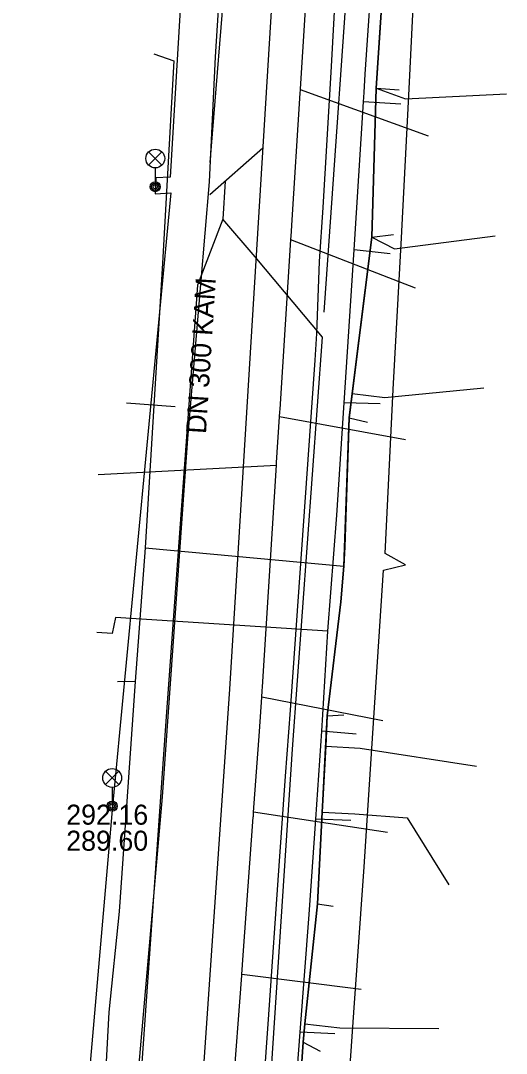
# Model space of a CAD drawing. Extents: x -595540 to -593988, y -1160850 to -1159202.
# Drawn here: x -594722.37 to -594702.98, y -1160244.04 to -1160202.8 of the extents above; entities that cross this region are included whole.
import ezdxf

# ---------------------------------------------------------------- set-up
doc = ezdxf.new("R2010")
doc.units = 0
for name, color, linetype in [('BVK-SPLASKOVA_popisy', 7, 'Continuous'), ('BVK-SPLASKOVA_trasa sítě', 7, 'Continuous'), ('BVK-VODOVOD_trasa sítě', 7, 'Continuous'), ('DSP-DESTOVA-BVK_trasa podzemní sítě', 7, 'Continuous'), ('DSP-SDEL-VODAFONE_kabel', 7, 'Continuous'), ('DSP-VODOVOD-BVK_trasa sítě', 7, 'Continuous'), ('EON-NN_kabel', 7, 'Continuous'), ('INNOGY-STL_trasa sítě', 7, 'Continuous'), ('SPLASKOVA_neprovozovaná  trasa sítě', 7, 'Continuous'), ('TSB_kabel VO', 7, 'Continuous'), ('TSB_lampy VO', 7, 'Continuous')]:
    doc.layers.add(name, color=color, linetype=linetype)

msp = doc.modelspace()

# ---------------------------------------------------------------- linework, layer by layer
at = {"layer": 'BVK-SPLASKOVA_popisy'}
msp.add_line((-594720.547, -1160234.111), (-594720.547, -1160234.111), dxfattribs=at)
at = {"layer": 'BVK-SPLASKOVA_trasa sítě'}
for points in [[(-594712.83, -1160231.19), (-594712.743, -1160229.818), (-594712.727, -1160229.566), (-594712.717, -1160229.404), (-594712.155, -1160220.556), (-594712.149, -1160220.462), (-594712.148, -1160220.445), (-594712.032, -1160218.619), (-594712.02, -1160218.426), (-594712.013, -1160218.316), (-594711.583, -1160211.559), (-594711.561, -1160211.22), (-594711.545, -1160210.968), (-594711.21, -1160205.691), (-594711.202, -1160205.559), (-594711.2, -1160205.521), (-594710.703, -1160197.698), (-594710.69, -1160197.488), (-594710.689, -1160197.479), (-594710.62, -1160196.39)], [(-594713.892, -1160245.671), (-594713.544, -1160240.935), (-594713.541, -1160240.891), (-594713.485, -1160240.126), (-594713.081, -1160234.611), (-594713.078, -1160234.574), (-594713.066, -1160234.406), (-594712.83, -1160231.19)]]:
    msp.add_lwpolyline(points, dxfattribs=at)
at = {"layer": 'BVK-VODOVOD_trasa sítě'}
msp.add_lwpolyline([(-594709.816, -1160201.699), (-594709.974, -1160204.626), (-594710.309, -1160210.266), (-594710.446, -1160212.418), (-594710.56, -1160215.3), (-594710.629, -1160216.362), (-594711.614, -1160230.332), (-594711.813, -1160232.98), (-594712.055, -1160236.55), (-594712.467, -1160242.489), (-594712.88, -1160248.322), (-594713.33, -1160254.72), (-594713.523, -1160257.981), (-594713.991, -1160263.88), (-594714.207, -1160266.837), (-594714.67, -1160272.908), (-594715.035, -1160278.113), (-594715.11, -1160279.01)], dxfattribs=at)
at = {"layer": 'DSP-DESTOVA-BVK_trasa podzemní sítě'}
for p, q in [((-594714.82, -1160209.75), (-594712.702, -1160207.877)), ((-594714.206, -1160209.207), (-594714.3, -1160210.73))]:
    msp.add_line(p, q, dxfattribs=at)
for points in [[(-594704.23, -1160062.12), (-594706.74, -1160074.53), (-594711.03, -1160081.92), (-594718.05, -1160094.02), (-594717.94, -1160110.41), (-594717.76, -1160137.04), (-594717.39, -1160159.05), (-594717.01, -1160181.31), (-594711.98, -1160196.12), (-594714.03, -1160229.5), (-594715.79, -1160255.02), (-594716.16, -1160260.4)], [(-594710.25, -1160214.442), (-594709.04, -1160197.18), (-594710.57, -1160191.56), (-594714.69, -1160189.7), (-594715.64, -1160189.34), (-594715.69, -1160190.57), (-594714.35, -1160196.02), (-594714.13, -1160200.12), (-594714.82, -1160208.46)], [(-594713.357, -1160259.91), (-594713.06, -1160255.38), (-594711.52, -1160231.9), (-594710.32, -1160215.44), (-594713.01, -1160212.23), (-594714.3, -1160210.73), (-594715.31, -1160213.36), (-594716.57, -1160230.78), (-594718.31, -1160255.59), (-594718.363, -1160256.34)]]:
    msp.add_lwpolyline(points, dxfattribs=at)
at = {"layer": 'DSP-SDEL-VODAFONE_kabel'}
for p, q in [((-594708.17, -1160205.5), (-594707.26, -1160205.57)), ((-594708.35, -1160211.45), (-594707.49, -1160211.34)), ((-594709.25, -1160218.66), (-594708.52, -1160218.83)), ((-594717.4, -1160223.86), (-594709.46, -1160224.59)), ((-594717.4, -1160223.86), (-594709.46, -1160224.59)), ((-594717.4, -1160223.86), (-594709.46, -1160224.59)), ((-594717.79, -1160229.19), (-594718.5, -1160229.21)), ((-594710.13, -1160230.56), (-594709.47, -1160230.52)), ((-594710.52, -1160238.07), (-594709.89, -1160238.17)), ((-594711.09, -1160243.59), (-594710.41, -1160243.96))]:
    msp.add_line(p, q, dxfattribs=at)
for points in [[(-594712.73, -1160179.59), (-594712.44, -1160181.67), (-594712.19, -1160183.44), (-594711.22, -1160185.82), (-594710.3, -1160187.87), (-594708.91, -1160190.02), (-594707.94, -1160192.21), (-594707.79, -1160194.31), (-594707.78, -1160199.43), (-594707.86, -1160200.65), (-594708.17, -1160205.5), (-594708.35, -1160211.45), (-594709.25, -1160218.66), (-594709.43, -1160223.82), (-594709.46, -1160224.59)], [(-594708.17, -1160205.5), (-594707.78, -1160199.43)], [(-594708.17, -1160205.5), (-594707.86, -1160200.65)], [(-594717.05, -1160204.12), (-594716.25, -1160204.41), (-594716.7, -1160212.48), (-594717.4, -1160223.86)], [(-594717.05, -1160204.12), (-594716.25, -1160204.41), (-594716.7, -1160212.48), (-594717.4, -1160223.86)], [(-594708.35, -1160211.45), (-594708.17, -1160205.5)], [(-594708.35, -1160211.45), (-594708.17, -1160205.5)], [(-594708.17, -1160205.5), (-594707, -1160205.92), (-594702.98, -1160205.73)], [(-594709.25, -1160218.66), (-594708.35, -1160211.45)], [(-594709.13, -1160217.69), (-594708.35, -1160211.45)], [(-594708.35, -1160211.45), (-594707.45, -1160211.91), (-594703.43, -1160211.4)], [(-594709.43, -1160223.82), (-594709.25, -1160218.66), (-594709.13, -1160217.69)], [(-594709.13, -1160217.69), (-594707.83, -1160217.85), (-594703.88, -1160217.46)], [(-594709.46, -1160224.59), (-594709.25, -1160218.66)], [(-594717.4, -1160223.86), (-594717.79, -1160229.19)], [(-594717.4, -1160223.86), (-594717.79, -1160229.19)], [(-594709.46, -1160224.59), (-594709.59, -1160226.01), (-594710.13, -1160230.56), (-594710.19, -1160231.78), (-594710.33, -1160234.41), (-594710.52, -1160238.07), (-594711.02, -1160242.87), (-594711.09, -1160243.59), (-594711.52, -1160249.84), (-594711.72, -1160252.62), (-594712.43, -1160262.29), (-594712.39, -1160262.83), (-594712.97, -1160268.59), (-594713.28, -1160274.83), (-594713.5, -1160280.21), (-594713.76, -1160282.85), (-594713.65, -1160283.35), (-594713.15, -1160283.56)], [(-594710.19, -1160231.78), (-594710.13, -1160230.56), (-594709.59, -1160226.01), (-594709.46, -1160224.59)], [(-594710.13, -1160230.56), (-594709.59, -1160226.01), (-594709.46, -1160224.59)], [(-594717.79, -1160229.19), (-594718.44, -1160238.38), (-594718.85, -1160242.4), (-594719.43, -1160253.27), (-594719.4, -1160253.59), (-594720.18, -1160253.56)], [(-594717.79, -1160229.19), (-594718.44, -1160238.38), (-594718.85, -1160242.4), (-594719.43, -1160253.27), (-594719.4, -1160253.59), (-594720.18, -1160253.56)], [(-594710.52, -1160238.07), (-594710.13, -1160230.56)], [(-594710.33, -1160234.41), (-594710.19, -1160231.78)], [(-594710.19, -1160231.78), (-594708.81, -1160231.86), (-594704.17, -1160232.57)], [(-594711.02, -1160242.87), (-594710.52, -1160238.07), (-594710.33, -1160234.41)], [(-594710.33, -1160234.41), (-594709.03, -1160234.48), (-594706.94, -1160234.64), (-594705.28, -1160237.31)], [(-594711.09, -1160243.59), (-594710.52, -1160238.07)], [(-594711.72, -1160252.62), (-594711.52, -1160249.84), (-594711.09, -1160243.59), (-594711.02, -1160242.87)], [(-594711.02, -1160242.87), (-594709.62, -1160243.02), (-594705.67, -1160243.05)], [(-594711.52, -1160249.84), (-594711.09, -1160243.59)]]:
    msp.add_lwpolyline(points, dxfattribs=at)
at = {"layer": 'DSP-VODOVOD-BVK_trasa sítě'}
msp.add_line((-594718.135, -1160218.069), (-594716.2, -1160218.208), dxfattribs=at)
at = {"layer": 'EON-NN_kabel'}
for points in [[(-594720.039, -1160120.667), (-594719.782, -1160133.42), (-594719.761, -1160133.936), (-594719.658, -1160139.618), (-594719.591, -1160150.069), (-594719.56, -1160162.08), (-594719.607, -1160167), (-594719.614, -1160167.25), (-594718.87, -1160174.172), (-594718.702, -1160182.569), (-594718.425, -1160185.217), (-594717.891, -1160187.194), (-594714.08, -1160196.106), (-594714.606, -1160204.241), (-594714.842, -1160209.239), (-594715.703, -1160219.483), (-594716.714, -1160233.804), (-594718.349, -1160252.557), (-594718.321, -1160254.817), (-594720.073, -1160280.009), (-594720.373, -1160279.998), (-594721.51, -1160281.51), (-594722.064, -1160281.517), (-594722.339, -1160281.408)], [(-594722.366, -1160281.584), (-594721.998, -1160281.716), (-594721.507, -1160281.71), (-594721.449, -1160281.634), (-594720.382, -1160280.235), (-594720.089, -1160280.24), (-594719.996, -1160280.873), (-594711.83, -1160282.703), (-594711.602, -1160279.521), (-594711.194, -1160273.462), (-594710.759, -1160267.349), (-594710.441, -1160262.269), (-594709.488, -1160248.553), (-594709.062, -1160242.418), (-594708.649, -1160236.597), (-594708.309, -1160231.252), (-594707.882, -1160224.747), (-594707, -1160224.529), (-594707.82, -1160224.085), (-594707.491, -1160217.538), (-594707.162, -1160211.48), (-594706.858, -1160205.528), (-594706.604, -1160200.359)]]:
    msp.add_lwpolyline(points, dxfattribs=at)
at = {"layer": 'INNOGY-STL_trasa sítě'}
for points in [[(-594713.82, -1160280.77), (-594713.8, -1160280.42), (-594713.4, -1160274.44), (-594713, -1160268.36), (-594712.97, -1160267.96), (-594712.61, -1160262.47), (-594712.36, -1160258.72), (-594712.03, -1160254.11), (-594712, -1160253.82), (-594711.94, -1160252.94), (-594711.76, -1160250.44), (-594711.21, -1160243.2), (-594710.85, -1160238.5), (-594710.58, -1160234.69), (-594710.34, -1160231.17), (-594710.1, -1160227.18), (-594709.74, -1160222.55), (-594709.45, -1160218.06), (-594709.06, -1160211.96), (-594708.68, -1160206.04), (-594708.66, -1160205.67), (-594708.61, -1160204.94), (-594708.28, -1160200.08)], [(-594707.19, -1160206.14), (-594708.68, -1160206.04)], [(-594707.62, -1160212.12), (-594709.06, -1160211.96)], [(-594708.01, -1160218.11), (-594709.45, -1160218.06)], [(-594718.58, -1160226.64), (-594718.72, -1160227.27), (-594719.33, -1160227.23)], [(-594710.1, -1160227.18), (-594718.58, -1160226.64)], [(-594708.97, -1160231.3), (-594710.34, -1160231.17)], [(-594709.19, -1160234.74), (-594710.58, -1160234.69)], [(-594709.82, -1160243.27), (-594711.21, -1160243.2)]]:
    msp.add_lwpolyline(points, dxfattribs=at)
at = {"layer": 'SPLASKOVA_neprovozovaná  trasa sítě'}
for p, q in [((-594706.09, -1160207.41), (-594711.202, -1160205.559)), ((-594706.61, -1160213.48), (-594711.583, -1160211.559)), ((-594707.01, -1160219.54), (-594712.032, -1160218.619)), ((-594719.27, -1160220.93), (-594712.155, -1160220.556)), ((-594707.91, -1160230.76), (-594712.743, -1160229.818)), ((-594707.72, -1160235.22), (-594713.066, -1160234.406)), ((-594708.78, -1160241.49), (-594713.541, -1160240.891))]:
    msp.add_line(p, q, dxfattribs=at)
at = {"layer": 'TSB_kabel VO'}
msp.add_lwpolyline([(-594715.593, -1160195.418), (-594716.399, -1160209.052), (-594716.977, -1160209.073), (-594716.998, -1160209.713), (-594716.378, -1160209.672), (-594718.7, -1160234.17), (-594720.303, -1160252.536), (-594720.35, -1160255.26), (-594721.832, -1160280.981), (-594722.17, -1160281)], dxfattribs=at)
at = {"layer": 'TSB_lampy VO'}
for p, q in [((-594717.258, -1160208.573), (-594716.728, -1160208.043)), ((-594717.258, -1160208.043), (-594716.728, -1160208.573)), ((-594717.258, -1160208.573), (-594716.728, -1160208.043)), ((-594717.258, -1160208.043), (-594716.728, -1160208.573)), ((-594716.993, -1160208.683), (-594716.993, -1160209.433)), ((-594716.993, -1160208.683), (-594716.993, -1160209.433)), ((-594718.979, -1160233.31), (-594718.449, -1160232.78)), ((-594718.979, -1160232.78), (-594718.449, -1160233.31)), ((-594718.979, -1160233.31), (-594718.449, -1160232.78)), ((-594718.979, -1160232.78), (-594718.449, -1160233.31)), ((-594718.714, -1160233.42), (-594718.714, -1160234.17)), ((-594718.714, -1160233.42), (-594718.714, -1160234.17))]:
    msp.add_line(p, q, dxfattribs=at)
for centre, radius in [((-594716.993, -1160208.308), 0.375), ((-594716.993, -1160208.308), 0.375), ((-594716.993, -1160209.433), 0.2), ((-594716.993, -1160209.433), 0.2), ((-594716.993, -1160209.433), 0.145), ((-594716.993, -1160209.433), 0.145), ((-594716.993, -1160209.433), 0.0876), ((-594716.993, -1160209.433), 0.0876), ((-594718.714, -1160233.045), 0.375), ((-594718.714, -1160233.045), 0.375), ((-594718.714, -1160234.17), 0.2), ((-594718.714, -1160234.17), 0.2), ((-594718.714, -1160234.17), 0.145), ((-594718.714, -1160234.17), 0.145), ((-594718.714, -1160234.17), 0.0876), ((-594718.714, -1160234.17), 0.0876)]:
    msp.add_circle(centre, radius, dxfattribs=at)

# ---------------------------------------------------------------- texts
at = {"layer": 'BVK-SPLASKOVA_popisy'}
msp.add_text('DN 300 KAM', height=0.8, rotation=86.3447, dxfattribs=at).set_placement((-594714.97, -1160219.318))
for s, p in [('292.16', (-594720.547, -1160234.911)), ('289.60', (-594720.547, -1160235.951))]:
    msp.add_text(s, height=0.8, dxfattribs=at).set_placement(p)

doc.saveas('drawing.dxf')
